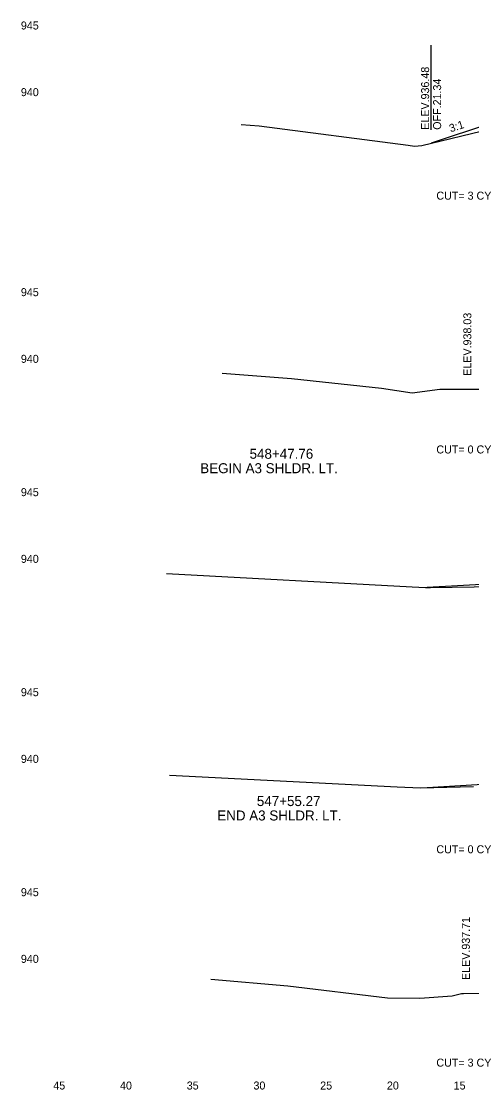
# Model space of a CAD drawing. Extents: x -4 to 359, y 0 to 1436.
# Drawn here: x 200.5 to 234.2, y 750.5 to 830.6 of the extents above; entities that cross this region are included whole.
import ezdxf

# ---------------------------------------------------------------- set-up
doc = ezdxf.new("R2010")
doc.units = 0
for name, color, linetype in [('XS-Existing surface-ground', 7, 'Continuous'), ('XS-Proposed surface-ground', 7, 'Continuous'), ('XS-Text-ditch slope', 7, 'Continuous'), ('XS-Text-earthwork labels', 7, 'Continuous'), ('XS-Text-elevation', 7, 'Continuous'), ('XS-Text-offset label', 7, 'Continuous'), ('XS-Text-profile report', 7, 'Continuous'), ('XS-Text-tie elevation', 7, 'Continuous'), ('XS-Text-tie offset', 7, 'Continuous')]:
    doc.layers.add(name, color=color, linetype=linetype)

msp = doc.modelspace()

# ---------------------------------------------------------------- linework, layer by layer
at = {"layer": 'XS-Existing surface-ground'}
for p, q in [((216.922, 822.856), (218.286, 822.746)), ((218.286, 822.746), (229.44, 821.292)), ((230.472, 821.289), (235.632, 822.524)), ((229.44, 821.292), (229.92, 821.217)), ((229.92, 821.217), (230.472, 821.289)), ((215.496, 804.209), (220.714, 803.79)), ((220.714, 803.79), (227.451, 803.079)), ((227.451, 803.079), (229.74, 802.72)), ((229.74, 802.72), (231.815, 802.994)), ((231.815, 802.994), (235.687, 803.01)), ((211.332, 789.18), (229.756, 788.169)), ((229.756, 788.169), (230.754, 788.132)), ((230.754, 788.132), (231.111, 788.127)), ((231.111, 788.127), (238.798, 788.253)), ((211.547, 774.059), (228.617, 773.177)), ((228.617, 773.177), (230.372, 773.093)), ((230.372, 773.093), (234.35, 773.207)), ((214.658, 758.761), (220.43, 758.26)), ((220.43, 758.26), (227.885, 757.363)), ((227.885, 757.363), (230.307, 757.329)), ((230.307, 757.329), (232.753, 757.506)), ((232.753, 757.506), (233.44, 757.674)), ((233.44, 757.674), (233.587, 757.672)), ((233.587, 757.672), (236.758, 757.705))]:
    msp.add_line(p, q, dxfattribs=at)
at = {"layer": 'XS-Proposed surface-ground'}
for points in [[(235.613, 822.923), (231.164, 821.455)], [(235.861, 788.41), (230.861, 788.131)], [(235.859, 773.402), (230.859, 773.107)]]:
    msp.add_lwpolyline(points, dxfattribs=at)
at = {"layer": 'XS-Text-tie offset'}
msp.add_line((231.164, 822.455), (231.164, 828.805), dxfattribs=at)

# ---------------------------------------------------------------- texts
at = {"layer": 'XS-Text-ditch slope'}
msp.add_text('3:1', height=0.6, rotation=18.26289, dxfattribs=at).set_placement((232.63, 822.255))
at = {"layer": 'XS-Text-earthwork labels'}
for s, height, p in [(' CUT= 3 CY           ', 0.6, (231.335, 817.215)), (' CUT= 0 CY           ', 0.6, (231.335, 798.181)), ('548+47.76', 0.75, (217.563, 797.782)), ('BEGIN A3 SHLDR. LT.', 0.75, (213.863, 796.7)), ('547+55.27', 0.75, (218.106, 771.736)), ('END A3 SHLDR. LT.', 0.75, (215.139, 770.655)), (' CUT= 0 CY           ', 0.6, (231.335, 768.194)), (' CUT= 3 CY           ', 0.6, (231.335, 752.194))]:
    msp.add_text(s, height=height, dxfattribs=at).set_placement(p)
at = {"layer": 'XS-Text-elevation'}
for s, p in [('           945           ', (197.97, 829.977)), ('           940           ', (197.97, 824.977)), ('           945           ', (197.97, 809.977)), ('           940           ', (197.97, 804.977)), ('           945           ', (197.97, 794.977)), ('           940           ', (197.97, 789.977)), ('           945           ', (197.97, 779.977)), ('           940           ', (197.97, 774.977)), ('           945           ', (197.97, 764.977)), ('           940           ', (197.97, 759.977))]:
    msp.add_text(s, height=0.6, dxfattribs=at).set_placement(p)
at = {"layer": 'XS-Text-offset label'}
for s, p in [('           45           ', (200.4, 750.477)), ('           40           ', (205.4, 750.477)), ('           35           ', (210.4, 750.477)), ('           30           ', (215.4, 750.477)), ('           25           ', (220.4, 750.477)), ('           20           ', (225.4, 750.477)), ('           15           ', (230.4, 750.477))]:
    msp.add_text(s, height=0.6, dxfattribs=at).set_placement(p)
at = {"layer": 'XS-Text-profile report'}
msp.add_text('Fill_Slope_2_B', height=0.00167, dxfattribs=at).set_placement((231.153, 821.454))
at = {"layer": 'XS-Text-tie elevation'}
for s, p in [('ELEV.936.48', (231.014, 822.455)), ('OFF.21.34', (231.914, 822.455)), ('ELEV.938.03', (234.18, 804.005)), ('ELEV.937.71', (234.068, 758.691))]:
    msp.add_text(s, height=0.6, rotation=90, dxfattribs=at).set_placement(p)

doc.saveas('drawing.dxf')
